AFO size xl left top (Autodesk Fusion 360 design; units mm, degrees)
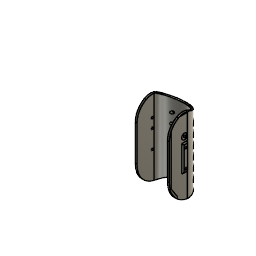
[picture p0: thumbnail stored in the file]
part number: 2025-10-02-12-56-12-317
parameter "d73" = 49
parameter "d131" = 16
sketch "Sketch1" plane through (0, 0, 0) normal (0, 0, 1) x axis (1, 0, 0)
  line L1 (28, -127.4) -> (-48, -127.4)
  line L2 (28, 0) -> (28, -127.4)
  line L3 (25, 0) -> (25, -127.4)
  line L4 (28, 0) -> (25, 0)
  line L5 (-18.603, -127.4) -> (-18.603, -115.6)
  line L6 (10.5, -127.4) -> (10.5, -109.9)
  line L7 (10.5, -127.4) -> (-18.603, -127.4)
  line L8 (36.7314, -101.9) -> (-43.9969, -101.9)
  line L9 (0, 0) -> (-28.984, 0)
  line L10 (-45, -127.4) -> (-25, 0)
  line L11 (-40.9969, -101.9) -> (-44.0794, -101.4161)
  line L12 (-48, -127.4) -> (-28, 0)
  line L13 (-43.6846, -101.9) -> (-43.6828, -102.2021)
  circle C1 centre (0, 0) radius 28
  circle C2 centre (0, 0) radius 25
  circle C3 centre (10.5, -109.9) radius 17.5
  circle C4 centre (-18.1846, -101.9) radius 22.5
  circle C5 centre (10.5, -109.9) radius 14.5
  circle C6 centre (-18.1846, -101.9) radius 25.5
  point P1 (0, 0)
  point P2 (0, 0)
  point P5 (28, 0)
  point P6 (0, 0)
  point P7 (25, 0)
  point P8 (25, -127.4)
  point P13 (-18.603, -127.4)
  point P11 (10.5, -109.9)
  point P14 (10.5, -109.9)
  point P15 (10.5, -127.4)
  point P20 (-25, 0)
  point P21 (-45, -127.4)
  point P22 (-40.9969, -101.9)
  point P10 (-18.1846, -101.9)
  point P25 (-28, 0)
  point P16 (-43.9969, -101.9)
  point P26 (-43.6828, -102.2021)
  point P27 (-43.6846, -101.9)
  point P19 (0, 0)
  coincident P1 P2
  coincident C1 P5
  tangent C1 L2
  perpendicular L1 L2
  coincident P1 P6
  vertical L3
  coincident C2 P7
  perpendicular L2 L4
  coincident L1 P8
  tangent L2 C3
  tangent L1 C3
  concentric C3 C5
  tangent L3 C5
  coincident L1 P13
  perpendicular L1 L5
  coincident P11 P14
  coincident L1 P15
  coincident C3 P15
  perpendicular L1 L6
  perpendicular L5 L8
  horizontal L9
  coincident C2 P20
  coincident L9 P20
  coincident L1 P21
  coincident L10 P22
  coincident L8 P22
  parallel L2 L3
  coincident P10 L8
  concentric C4 C6
  coincident L9 P25
  coincident C1 P25
  parallel L10 L12
  coincident P16 L12
  coincident C6 P26
  coincident L8 P27
  coincident C6 P27
  coincident P1 P19
  tangent L1 C6
  tangent C6 L12
  perpendicular L11 L12
  dimension "d2" diameter C1 = 56 (= "d57 + ( 3 * 2 ) * 1 mm")
  dimension "d4" distance P2 L1 = 127.4 (= "152.4 mm - 25 mm")
  dimension "d57" diameter C2 = 50
  dimension "d74" diameter C3 = 35
  dimension "d252" diameter C4 = 45 (= "d73 - 4 mm")
  dimension "d322" distance P8 P21 = 70
  dimension "d323" diameter C6 = 51 (= "d252 + 6 mm")
extrude "Extrude1" new body sketch "Sketch1" profile of C1 L2 L3 L4 C3 L8 L9 L10 L11 C6 L12 along normal blind 35
extrude "Extrude2" add sketch "Sketch1" profile of C1 L1 L2 C2 L3 C3 C4 C5 L5 L6 L7 L8 L10 L11 C6 L13 along normal blind 3
extrude "Extrude15" new body sketch "Sketch1" profile of C1 C2 L4 L9 along normal blind 178
combine "Combine2"
work_plane "WorkPlane1" RotateAngle -90
fillet "Fillet69" radius 1 1
sketch "Sketch23" plane through (28, 0, 0) normal (1, 0, 0) x axis (0, 1, 0)
  line L1 (-28, 78) -> (0, 35)
  line L2 (-28, 178) -> (-28, 78)
  line L3 (0, 178) -> (-28, 178)
  line L4 (0, 35) -> (0, 178)
  circle C1 centre (-3, 143) radius 1.75
  point P5 (0, 178)
  point P6 (0, 178)
  point P2 (0, 35)
  point P8 (0, 35)
  point P4 (-28, 178)
  point P3 (-28, 78)
  point P7 (-3, 143)
  horizontal L3
  perpendicular L3 L4
  coincident P5 P6
  coincident P2 P8
  parallel L2 L4
  dimension "d253" distance P4 P5 = 28
  dimension "d254" distance P3 P4 = 100
  dimension "d255" diameter C1 = 3.5
  dimension "d256" distance L3 P7 = 35
  dimension "d257" distance L2 P7 = 25
extrude "Extrude18" add sketch "Sketch23" against normal blind 3
mirror "Mirror1" mirrorStitchTolerance 0.1
sketch "Sketch24" plane through (0, 16.0046, 10.4216) normal (0, -0.838, -0.5457) x axis (1, 0, 0)
  line L1 (-25, 80.6427) -> (-25, 29.3299)
  line L2 (-28, 80.6427) -> (-25, 80.6427)
  line L3 (-28, 29.3299) -> (-28, 80.6427)
  line L4 (-25, 62.182) -> (-28, 62.182)
  line L5 (-28, 30.2476) -> (-25, 30.2476)
  line L6 (-28, 30.2476) -> (-28, 62.182)
  line L7 (-25, 62.182) -> (-25, 30.2476)
  line L8 (-25, 29.3299) -> (-28, 29.3299)
  point P6 (-28, 62.182)
  point P7 (-25, 62.182)
  point P8 (-25, 30.2476)
  point P9 (-28, 30.2476)
  coincident L3 P6
  coincident L1 P7
  perpendicular L1 L4
  coincident L1 P8
  coincident L3 P9
  perpendicular L3 L5
sketch "Sketch25" plane through (0, 0, 35) normal (0, 0, 1) x axis (-1, 0, 0)
  line L1 (24.843, -1) -> (27.843, -1)
  line L2 (29.5678, 29.0967) -> (24.843, -1)
  line L3 (32.4956, 28.637) -> (29.5678, 29.0967)
  line L4 (32.4956, 28.637) -> (27.843, -1)
  line L5 (0, 0) -> (28.984, 0)
  line L6 (43.3761, 97.9455) -> (28, 0)
  line L7 (25, 0) -> (40.9969, 101.9)
  line L8 (28, 0) -> (25, 0)
  line L9 (40.9969, 101.9) -> (43.6811, 101.4786)
  arc A1 centre (18.1846, 101.9) radius 25.5 clockwise from (43.6811, 101.4786) to (43.3761, 97.9455)
  point P5 (32.4956, 28.637)
  point P4 (29.5678, 29.0967)
  point P15 (28, 0)
  point P8 (25, 0)
  point P2 (27.843, -1)
  horizontal L1
  coincident P5 L6
  coincident P4 L7
  coincident L4 P15
  coincident L2 P8
  perpendicular L3 L4
  dimension "d280" distance P2 P5 = 30
  dimension "d281" distance L1 L5 = 1
loft "Loft1" sketch "Sketch24" + "Sketch25"
sketch "Sketch26" plane through (0, 0, 35) normal (0, 0, 1) x axis (-1, 0, 0)
  line L1 (-28, 0) -> (-28, 101.9)
  line L2 (-25, 0) -> (-28, 0)
  line L3 (-28, -1) -> (-25, -1)
  line L4 (-28, -1) -> (-28, 29)
  line L5 (-25, 29) -> (-28, 29)
  line L6 (-25, -1) -> (-25, 29)
  line L7 (-28, 101.9) -> (-25, 101.9)
  line L8 (-25, 101.9) -> (-25, 0)
  point P5 (-28, -1)
  point P6 (-28, 29)
  point P7 (-25, 29)
  coincident L1 P5
  perpendicular L1 L3
  coincident L1 P6
  coincident P7 L8
  dimension "d278" distance P5 P6 = 30
  dimension "d279" distance L2 L3 = 1
sketch "Sketch27" plane through (0, 16.0046, 10.4216) normal (0, -0.838, -0.5457) x axis (1, 0, 0)
  line L1 (28, 80.6427) -> (28, 29.3299)
  line L2 (25, 80.6427) -> (28, 80.6427)
  line L3 (25, 29.3299) -> (25, 80.6427)
  line L4 (28, 29.3299) -> (25, 29.3299)
  line L5 (28, 63.1164) -> (25, 63.1164)
  line L6 (28, 32.1164) -> (28, 63.1164)
  line L7 (28, 32.1164) -> (25, 32.1164)
  line L8 (25, 63.1164) -> (25, 32.1164)
  point P6 (25, 63.1164)
  point P7 (28, 63.1164)
  point P8 (28, 32.1164)
  point P9 (25, 32.1164)
  coincident L3 P6
  coincident L1 P7
  perpendicular L1 L5
  coincident L1 P8
  coincident L3 P9
  perpendicular L6 L7
  dimension "d282" distance P7 P8 = 31
loft "Loft2" sketch "Sketch27" + "Sketch26"
work_plane "WorkPlane4" AlongDistance 28 (= "25 mm + 3 mm")
sketch "Sketch9" plane through (0, 28, 0) normal (0, 1, 0) x axis (1, 0, 0)
  circle C1 centre (0, -16) radius 2.25
  circle C2 centre (0, -32) radius 2.25
  circle C3 centre (0, -64) radius 2.25
  circle C4 centre (0, -96) radius 2.25
  circle C5 centre (0, -80) radius 2.25
  circle C6 centre (0, -112) radius 2.25
  circle C7 centre (0, -128) radius 2.25
  circle C8 centre (0, -144) radius 2.25
  point P2 (0, -16)
  point P7 (0, 0)
  point P3 (0, -32)
  point P4 (0, -64)
  point P6 (0, -80)
  point P5 (0, -96)
  point P8 (0, -112)
  point P9 (0, -128)
  point P10 (0, -144)
  dimension "d123" diameter C1 = 4.5
  dimension "d124" diameter C2 = 4.5
  dimension "d126" diameter C3 = 4.5
  dimension "d127" diameter C4 = 4.5
  dimension "d128" diameter C5 = 4.5
  dimension "d129" distance P2 P7 = 16
  dimension "d130" distance P2 P3 = 16
  dimension "d133" distance P4 P6 = 16 (= "d131")
  dimension "d134" distance P5 P6 = 16 (= "d131")
  dimension "d291" diameter C6 = 4.5
  dimension "d292" distance P5 P8 = 16 (= "d131")
  dimension "d293" distance P8 P9 = 16 (= "d130")
  dimension "d294" diameter C7 = 4.5
  dimension "d295" diameter C8 = 4.5
  dimension "d296" distance P9 P10 = 16 (= "d131")
extrude "Extrude20" cut sketch "Sketch9" against normal blind 30
path_pattern "PathPattern3" PathPatternDelta 88.0394
fillet "Fillet51" radius 7 15
fillet "Fillet52" radius 130 130
sphere_primitive "SpherePrimitive3" Diameter 55
move_face "MoveFace3"
boundary_fill "BoundaryFill2"
offset_faces "OffsetFaces2" distance 3
shell "Shell7" innerThickness 2.99
fillet "Fillet74" radius 10 15
hole "Hole6" HoleDepth 106.033 HoleDiameter 3.5 TipAngle 118
hole "Hole7" HoleDepth 106.033 HoleDiameter 3.5 TipAngle 118
work_plane "WorkPlane5" AlongDistance 100
work_plane "WorkPlane6" AlongDistance 51.6037
fillet "Fillet76" radius 30
fillet "Fillet79" radius 25
fillet "Fillet83" radius 22
fillet "Fillet85" radius 30 30
fillet "Fillet86" radius 45
split "Split1"
work_plane "WorkPlane7" AlongDistance -28 (= "-( 56 / 2 ) * 1 mm")
sketch "Sketch35" plane through (-28, 0, 0) normal (1, 0, 0) x axis (0, 1, 0)
  circle C1 centre (-2.7874, 31.4508) radius 6
  dimension "d426" diameter C1 = 12
extrude "Extrude22" add sketch "Sketch35" against normal blind 2
fillet "Fillet87" radius 35
sketch "Sketch33" plane through (27.99, 0, 0) normal (1, 0, 0) x axis (0, 1, 0)
  line L1 (0, 139.3302) -> (0, 52.395)
  line L2 (0, 175.01) -> (0, 146.6698)
  line L3 (-11.056, 175.01) -> (0, 175.01)
  line L4 (-25.01, 78.8877) -> (-25.01, 161.056)
  line L5 (-15.1078, 63.6808) -> (-25.01, 78.8877)
  line L6 (-16.1988, 60.7566) -> (-15.1078, 63.6808)
  line L7 (2, 178) -> (28, 178)
  arc A1 centre (7.4005, 86.6037) radius 35 clockwise from (0, 52.395) to (-16.1988, 60.7566)
  arc A2 centre (-3, 143) radius 4.74 clockwise from (0, 139.3302) to (0, 146.6698)
  arc A3 centre (2, 148) radius 30 clockwise from (-25.01, 161.056) to (-11.056, 175.01)
  circle C1 centre (-3, 128) radius 1.75
  circle C2 centre (-3, 98) radius 1.75
  circle C3 centre (-3, 32) radius 1.75
  point P16 (-3, 128)
  point P17 (-3, 98)
  point P18 (-3, 32)
  vertical P16 P17
  vertical P17 P18
  dimension "d413" diameter C1 = 3.5
  dimension "d414" distance P16 P17 = 30
  dimension "d415" diameter C3 = 3.5
  dimension "d416" distance P17 P18 = 66
  dimension "d417" distance P16 L7 = 50
  dimension "d418" distance L1 P16 = 3
  dimension "d480" diameter C2 = 3.5
extrude "Extrude21" cut sketch "Sketch33" profile of C1 C2 C3 against normal blind 133.937
fillet "Fillet88" radius 36
sketch "Sketch37" plane through (-28, 0, 0) normal (1, 0, 0) x axis (0, 1, 0)
fillet "Fillet98" radius 48
fillet "Fillet99" radius 48
sketch "Sketch38" plane through (-28, 0, 0) normal (1, 0, 0) x axis (0, 1, 0)
  line L1 (-5.5406, 132.8689) -> (0, 132.8689)
  line L2 (-5.5406, 93.572) -> (-5.5406, 132.8689)
  line L3 (0, 93.572) -> (-5.5406, 93.572)
  line L4 (0, 132.8689) -> (0, 93.572)
  horizontal L1
  vertical L2
  horizontal L3
  vertical L4
extrude "Extrude24" add sketch "Sketch38" along normal blind 1 and against normal blind 2
fillet "Fillet91" radius 2 2 2 2
fillet "Fillet92" radius 0.5
extrude "Extrude25" cut sketch "Sketch33" profile of C1 C2 against normal blind 188.494
work_plane "WorkPlane8" AlongDistance 178
sketch "Sketch39" plane through (0, 0, 178) normal (0, 0, 1) x axis (1, 0, 0)
  line L1 (-25, 0) -> (25, 0)
  line L2 (30, 0) -> (25, 0)
  line L3 (-32, 0) -> (-25, 0)
  arc A1 centre (0, 10.2) radius 29.8 clockwise from (-28, 0) to (28, 0)
  point P7 (-28, 0)
  horizontal L1
  parallel L1 L2
  parallel L1 L3
  coincident L3 P7
revolve "Revolve2" sketch "Sketch39" AlongAngle -30
fillet "Fillet95" radius 20 20
fillet "Fillet101" radius 1
fillet "Fillet97" radius 1.5
mirror "Mirror4" mirrorStitchTolerance 0.1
